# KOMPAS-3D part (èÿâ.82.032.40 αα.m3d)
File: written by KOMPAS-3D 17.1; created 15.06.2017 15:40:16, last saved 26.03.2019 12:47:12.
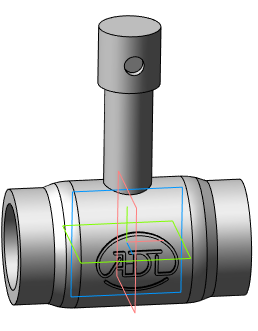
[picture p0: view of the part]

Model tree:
1. Операция без истории:2  (labels: Сталь 20  ГОСТ 1050-88)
